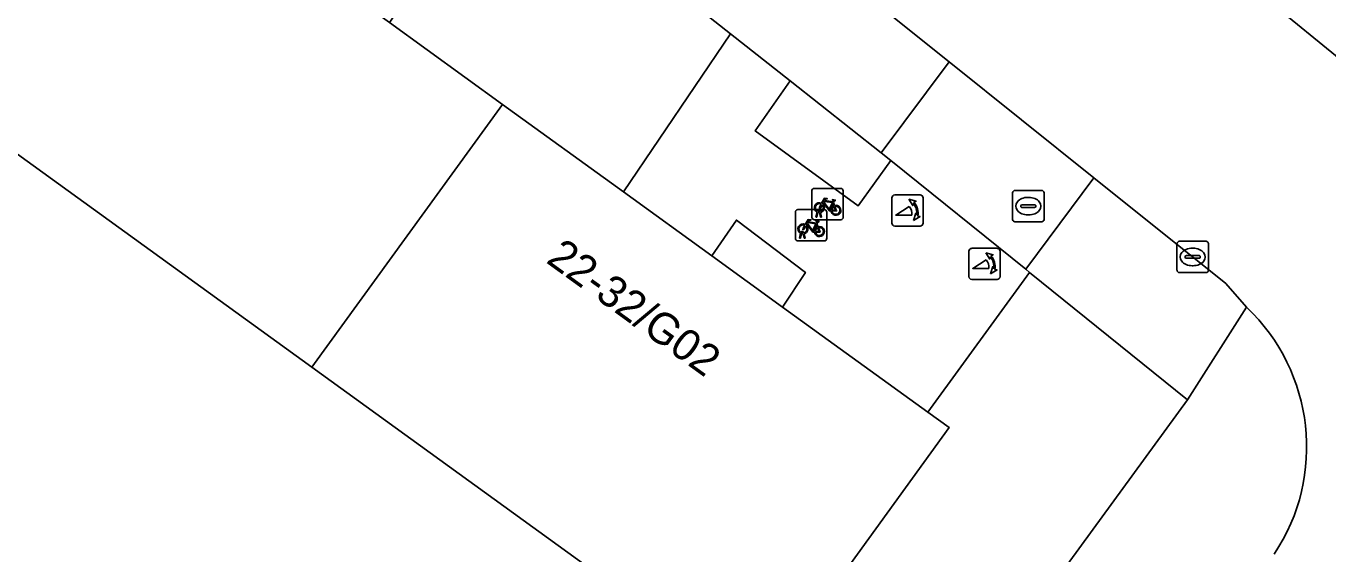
# Model space of a CAD drawing. Extents: x 159674 to 160531, y 382172 to 382904.
# Drawn here: x 160362.08 to 160403.62, y 382615.6 to 382632.46 of the extents above; entities that cross this region are included whole.
import ezdxf

# ---------------------------------------------------------------- set-up
doc = ezdxf.new("R2010")
doc.units = 0
for name, color, linetype in [('IMGEO_Brandkraan', 7, 'Continuous'), ('IMGEO_Fietsenrek', 7, 'Continuous'), ('IMGEO_Groenvoorziening', 7, 'Continuous'), ('IMGEO_Kolk', 7, 'Continuous'), ('IMGEO_Pand', 7, 'Continuous'), ('IMGEO_Pand_nummerreeks', 7, 'Continuous'), ('IMGEO_Poller', 7, 'Continuous'), ('IMGEO_Rijbaan_lokaal_gesloten', 7, 'Continuous'), ('IMGEO_Voetpad_open', 7, 'Continuous')]:
    doc.layers.add(name, color=color, linetype=linetype)

msp = doc.modelspace()

# ---------------------------------------------------------------- linework, layer by layer
at = {"layer": 'IMGEO_Brandkraan'}
for p, q in [((160393.557, 382626.284), (160393.557, 382627.136)), ((160393.632, 382627.21), (160394.484, 382627.21)), ((160394.558, 382627.136), (160394.558, 382626.284)), ((160393.816, 382626.704), (160393.816, 382626.716)), ((160394.254, 382626.667), (160393.856, 382626.667)), ((160393.859, 382626.753), (160394.257, 382626.753)), ((160394.045, 382626.99), (160394.07, 382626.99)), ((160394.3, 382626.716), (160394.3, 382626.704)), ((160394.484, 382626.21), (160393.632, 382626.21)), ((160394.068, 382626.43), (160394.043, 382626.43))]:
    msp.add_line(p, q, dxfattribs=at)
for points in [[(160393.557, 382626.284), (160393.557, 382627.136)], [(160393.632, 382627.21), (160394.484, 382627.21)], [(160394.558, 382627.136), (160394.558, 382626.284)], [(160394.484, 382626.21), (160393.632, 382626.21)]]:
    msp.add_lwpolyline(points, dxfattribs=at)
for centre, radius, start, end in [((160393.634, 382627.134), 0.0765, 91.552, 178.448), ((160393.634, 382627.134), 0.0765, 91.552, 178.448), ((160394.482, 382627.134), 0.0765, 1.552, 88.448), ((160394.482, 382627.134), 0.0765, 1.552, 88.448), ((160393.856, 382626.713), 0.0403, 85.8775, 175.7526), ((160393.853, 382626.703), 0.0366, 178.938, 274.7102), ((160394.257, 382626.71), 0.043, 264.8664, 352.4533), ((160394.261, 382626.715), 0.0386, 1.7309, 96.639), ((160393.634, 382626.286), 0.0765, 181.552, 268.448), ((160393.634, 382626.286), 0.0765, 181.552, 268.448), ((160394.482, 382626.286), 0.0765, 271.552, 358.448), ((160394.482, 382626.286), 0.0765, 271.552, 358.448)]:
    msp.add_arc(centre, radius, start, end, dxfattribs=at)
for centre, major_axis, ratio, start_param, end_param in [((160394.044, 382626.71), (-0.387, 0.002), 0.722429, 4.712389, 7.853982), ((160394.069, 382626.71), (-0.39, 0.002), 0.717154, 1.570796, 4.712389)]:
    msp.add_ellipse(centre, major_axis=major_axis, ratio=ratio, start_param=start_param, end_param=end_param, dxfattribs=at)
at = {"layer": 'IMGEO_Fietsenrek'}
for p, q in [((160387.15, 382626.351), (160387.15, 382627.192)), ((160387.15, 382627.192), (160387.15, 382626.351)), ((160387.225, 382627.276), (160388.066, 382627.276)), ((160388.066, 382627.276), (160387.225, 382627.276)), ((160388.15, 382627.201), (160388.15, 382626.36)), ((160388.15, 382626.36), (160388.15, 382627.201)), ((160387.837, 382626.825), (160387.873, 382626.73)), ((160386.625, 382625.673), (160386.625, 382626.514)), ((160386.625, 382626.514), (160386.625, 382625.673)), ((160386.7, 382626.598), (160387.541, 382626.598)), ((160387.541, 382626.598), (160386.7, 382626.598)), ((160388.075, 382626.276), (160387.234, 382626.276)), ((160387.234, 382626.276), (160388.075, 382626.276)), ((160387.277, 382626.36), (160387.316, 382626.52)), ((160387.311, 382626.36), (160387.277, 382626.36)), ((160387.346, 382626.508), (160387.311, 382626.36)), ((160387.388, 382626.532), (160387.387, 382626.536)), ((160387.429, 382626.36), (160387.395, 382626.502)), ((160387.419, 382626.543), (160387.42, 382626.536)), ((160387.427, 382626.506), (160387.462, 382626.36)), ((160387.462, 382626.36), (160387.429, 382626.36)), ((160387.625, 382626.523), (160387.625, 382625.682)), ((160387.625, 382625.682), (160387.625, 382626.523)), ((160386.752, 382625.682), (160386.791, 382625.842)), ((160386.821, 382625.83), (160386.786, 382625.682)), ((160386.863, 382625.854), (160386.862, 382625.858)), ((160386.904, 382625.682), (160386.87, 382625.824)), ((160386.894, 382625.865), (160386.895, 382625.858)), ((160386.902, 382625.828), (160386.937, 382625.682)), ((160387.312, 382626.147), (160387.348, 382626.052)), ((160387.55, 382625.598), (160386.709, 382625.598)), ((160386.709, 382625.598), (160387.55, 382625.598)), ((160386.786, 382625.682), (160386.752, 382625.682)), ((160386.937, 382625.682), (160386.904, 382625.682))]:
    msp.add_line(p, q, dxfattribs=at)
for points in [[(160387.484, 382626.75), (160387.432, 382626.66), (160387.392, 382626.635), (160387.393, 382626.682), (160387.448, 382626.776)], [(160387.463, 382626.802), (160387.558, 382626.966), (160387.644, 382626.952), (160387.646, 382626.943), (160387.59, 382626.932), (160387.563, 382626.887), (160387.819, 382626.846)], [(160387.759, 382626.558), (160387.709, 382626.558), (160387.518, 382626.809), (160387.499, 382626.777)], [(160387.806, 382626.821), (160387.549, 382626.862), (160387.532, 382626.833), (160387.699, 382626.613), (160387.806, 382626.821)], [(160387.854, 382626.723), (160387.824, 382626.8), (160387.715, 382626.582), (160387.758, 382626.582)], [(160387.788, 382626.582), (160387.908, 382626.581), (160387.864, 382626.695)], [(160387.884, 382626.702), (160387.939, 382626.557), (160387.789, 382626.557)], [(160387.819, 382626.846), (160387.844, 382626.895), (160387.838, 382626.899), (160387.815, 382626.903), (160387.803, 382626.91), (160387.802, 382626.913), (160387.804, 382626.918), (160387.899, 382626.903), (160387.901, 382626.893), (160387.891, 382626.88), (160387.879, 382626.874), (160387.865, 382626.88), (160387.837, 382626.825)], [(160386.938, 382626.124), (160387.033, 382626.288), (160387.119, 382626.274), (160387.121, 382626.265), (160387.065, 382626.254), (160387.038, 382626.209), (160387.294, 382626.168)], [(160387.294, 382626.168), (160387.319, 382626.217), (160387.313, 382626.221), (160387.29, 382626.225), (160387.278, 382626.232), (160387.277, 382626.235), (160387.279, 382626.24), (160387.374, 382626.225), (160387.376, 382626.215), (160387.366, 382626.202), (160387.354, 382626.196), (160387.34, 382626.202), (160387.312, 382626.147)], [(160386.959, 382626.072), (160386.907, 382625.982), (160386.867, 382625.957), (160386.868, 382626.004), (160386.923, 382626.098)], [(160387.234, 382625.88), (160387.184, 382625.88), (160386.993, 382626.131), (160386.974, 382626.099)], [(160387.281, 382626.143), (160387.024, 382626.184), (160387.007, 382626.155), (160387.174, 382625.935), (160387.281, 382626.143)], [(160387.329, 382626.045), (160387.299, 382626.122), (160387.19, 382625.904), (160387.233, 382625.904)], [(160387.263, 382625.904), (160387.383, 382625.903), (160387.339, 382626.017)], [(160387.359, 382626.024), (160387.414, 382625.879), (160387.264, 382625.879)]]:
    msp.add_lwpolyline(points, dxfattribs=at)
for centre, radius, start, end in [((160387.228, 382627.198), 0.0779, 92.4484, 184.2845), ((160387.228, 382627.198), 0.0779, 92.4484, 184.2845), ((160388.072, 382627.198), 0.0779, 2.4484, 94.2845), ((160388.072, 382627.198), 0.0779, 2.4484, 94.2845), ((160387.39, 382626.661), 0.159, 62.6766, 242.1369), ((160387.39, 382626.661), 0.129, 63.3192, 238.903), ((160387.39, 382626.661), 0.129, 283.6043, 43.4302), ((160387.39, 382626.661), 0.159, 283.5766, 46.6042), ((160387.917, 382626.577), 0.159, 113.3408, 178.3217), ((160387.917, 382626.577), 0.159, 187.0065, 105.7708), ((160387.917, 382626.577), 0.129, 113.923, 177.9556), ((160387.917, 382626.577), 0.129, 188.6715, 104.5883), ((160386.703, 382626.52), 0.0779, 92.4484, 184.2845), ((160386.703, 382626.52), 0.0779, 92.4484, 184.2845), ((160387.228, 382626.354), 0.0779, 182.4484, 274.2845), ((160387.228, 382626.354), 0.0779, 182.4484, 274.2845), ((160387.37, 382626.532), 0.0499, 12.8025, 158.6934), ((160387.39, 382626.661), 0.159, 253.9967, 271.7867), ((160387.37, 382626.532), 0.0174, 12.8025, 163.4502), ((160387.39, 382626.661), 0.129, 253.415, 269.0204), ((160387.547, 382626.52), 0.0779, 2.4484, 94.2845), ((160387.547, 382626.52), 0.0779, 2.4484, 94.2845), ((160388.072, 382626.354), 0.0779, 272.4484, 4.2845), ((160388.072, 382626.354), 0.0779, 272.4484, 4.2845), ((160386.865, 382625.983), 0.159, 62.6766, 242.1369), ((160386.865, 382625.983), 0.129, 63.3192, 238.903), ((160386.845, 382625.854), 0.0499, 12.8025, 158.6934), ((160386.865, 382625.983), 0.159, 253.9967, 271.7867), ((160386.845, 382625.854), 0.0174, 12.8025, 163.4502), ((160386.865, 382625.983), 0.129, 253.415, 269.0204), ((160386.865, 382625.983), 0.129, 283.6043, 43.4302), ((160386.865, 382625.983), 0.159, 283.5766, 46.6042), ((160387.392, 382625.899), 0.159, 113.3408, 178.3217), ((160387.392, 382625.899), 0.159, 187.0065, 105.7708), ((160387.392, 382625.899), 0.129, 113.923, 177.9556), ((160387.392, 382625.899), 0.129, 188.6715, 104.5883), ((160386.703, 382625.676), 0.0779, 182.4484, 274.2845), ((160386.703, 382625.676), 0.0779, 182.4484, 274.2845), ((160387.547, 382625.676), 0.0779, 272.4484, 4.2845), ((160387.547, 382625.676), 0.0779, 272.4484, 4.2845)]:
    msp.add_arc(centre, radius, start, end, dxfattribs=at)
at = {"layer": 'IMGEO_Groenvoorziening'}
for points in [[(160399.135, 382620.521), (160394.097, 382624.593), (160390.852, 382620.13), (160391.536, 382619.635), (160385.454, 382611.238), (160381.405, 382614.171), (160371.199, 382621.562), (160356.943, 382631.886), (160360.093, 382636.235), (160363.025, 382640.284), (160363.685, 382639.806), (160368.154, 382645.167), (160368.401, 382645.464), (160368.041, 382645.751), (160367.072, 382646.525), (160363.098, 382641.755), (160342.684, 382657.705), (160337.191, 382650.136), (160341.198, 382647.23), (160341.661, 382647.868), (160350.057, 382641.78), (160339.718, 382627.522), (160329.387, 382613.273)], [(160343.467, 382554.933), (160344.044, 382554.45), (160341.99, 382551.571), (160346.474, 382548.259), (160399.135, 382620.521)]]:
    msp.add_lwpolyline(points, dxfattribs=at)
for points in [[(160384.552, 382632.213), (160377.395, 382637.867), (160373.677, 382632.57), (160377.281, 382629.959), (160381.138, 382627.166)], [(160386.458, 382630.707), (160385.343, 382629.114), (160388.624, 382626.718), (160389.672, 382628.168), (160389.367, 382628.409)], [(160386.216, 382623.488), (160386.946, 382624.592), (160384.743, 382626.263), (160383.956, 382625.125)]]:
    msp.add_lwpolyline(points, close=True, dxfattribs=at)
at = {"layer": 'IMGEO_Kolk'}
for p, q in [((160398.801, 382624.66), (160398.801, 382625.512)), ((160398.876, 382625.586), (160399.728, 382625.586)), ((160399.802, 382625.512), (160399.802, 382624.66)), ((160399.06, 382625.08), (160399.06, 382625.092)), ((160399.498, 382625.043), (160399.1, 382625.043)), ((160399.103, 382625.129), (160399.501, 382625.129)), ((160399.289, 382625.366), (160399.314, 382625.366)), ((160399.544, 382625.092), (160399.544, 382625.08)), ((160399.728, 382624.586), (160398.876, 382624.586)), ((160399.312, 382624.806), (160399.287, 382624.806))]:
    msp.add_line(p, q, dxfattribs=at)
for points in [[(160398.801, 382624.66), (160398.801, 382625.512)], [(160398.876, 382625.586), (160399.728, 382625.586)], [(160399.802, 382625.512), (160399.802, 382624.66)], [(160399.728, 382624.586), (160398.876, 382624.586)]]:
    msp.add_lwpolyline(points, dxfattribs=at)
for centre, radius, start, end in [((160398.878, 382625.51), 0.0765, 91.552, 178.448), ((160398.878, 382625.51), 0.0765, 91.552, 178.448), ((160399.726, 382625.51), 0.0765, 1.552, 88.448), ((160399.726, 382625.51), 0.0765, 1.552, 88.448), ((160399.1, 382625.089), 0.0403, 85.8775, 175.7526), ((160399.097, 382625.079), 0.0366, 178.938, 274.7102), ((160399.501, 382625.086), 0.043, 264.8664, 352.4533), ((160399.505, 382625.091), 0.0386, 1.7309, 96.639), ((160398.878, 382624.662), 0.0765, 181.552, 268.448), ((160398.878, 382624.662), 0.0765, 181.552, 268.448), ((160399.726, 382624.662), 0.0765, 271.552, 358.448), ((160399.726, 382624.662), 0.0765, 271.552, 358.448)]:
    msp.add_arc(centre, radius, start, end, dxfattribs=at)
for centre, major_axis, ratio, start_param, end_param in [((160399.288, 382625.086), (-0.387, 0.002), 0.722429, 4.712389, 7.853982), ((160399.313, 382625.086), (-0.39, 0.002), 0.717154, 1.570796, 4.712389)]:
    msp.add_ellipse(centre, major_axis=major_axis, ratio=ratio, start_param=start_param, end_param=end_param, dxfattribs=at)
at = {"layer": 'IMGEO_Pand'}
for points in [[(160371.199, 382621.562), (160377.281, 382629.959), (160373.677, 382632.57), (160370.844, 382634.621), (160368.647, 382636.212), (160363.685, 382639.806), (160363.025, 382640.284), (160360.093, 382636.235), (160356.943, 382631.886)], [(160371.199, 382621.562), (160381.405, 382614.171), (160385.454, 382611.238), (160391.536, 382619.635), (160390.852, 382620.13), (160386.216, 382623.488), (160383.956, 382625.125), (160381.138, 382627.166), (160377.281, 382629.959)]]:
    msp.add_lwpolyline(points, close=True, dxfattribs=at)
at = {"layer": 'IMGEO_Poller'}
for p, q in [((160390.605, 382627.07), (160389.797, 382627.07)), ((160390.605, 382627.07), (160389.797, 382627.07)), ((160389.703, 382626.975), (160389.703, 382626.168)), ((160389.703, 382626.975), (160389.703, 382626.168)), ((160390.699, 382626.168), (160390.699, 382626.975)), ((160390.699, 382626.168), (160390.699, 382626.975)), ((160389.797, 382626.073), (160390.605, 382626.073)), ((160389.797, 382626.073), (160390.605, 382626.073)), ((160392.16, 382625.267), (160392.16, 382624.46)), ((160392.16, 382625.267), (160392.16, 382624.46)), ((160393.062, 382625.362), (160392.254, 382625.362)), ((160393.062, 382625.362), (160392.254, 382625.362)), ((160393.156, 382624.46), (160393.156, 382625.267)), ((160393.156, 382624.46), (160393.156, 382625.267)), ((160392.254, 382624.365), (160393.062, 382624.365)), ((160392.254, 382624.365), (160393.062, 382624.365))]:
    msp.add_line(p, q, dxfattribs=at)
for points in [[(160390.338, 382626.426), (160389.825, 382626.426), (160390.255, 382626.701)], [(160390.382, 382626.799), (160390.37, 382626.726), (160390.245, 382626.931)], [(160390.245, 382626.931), (160390.476, 382626.865), (160390.405, 382626.833)], [(160390.398, 382626.254), (160390.464, 382626.485), (160390.494, 382626.417)], [(160390.53, 382626.39), (160390.602, 382626.379), (160390.398, 382626.254)], [(160392.795, 382624.718), (160392.282, 382624.718), (160392.712, 382624.993)], [(160392.839, 382625.091), (160392.827, 382625.018), (160392.702, 382625.223)], [(160392.702, 382625.223), (160392.933, 382625.157), (160392.862, 382625.125)], [(160392.855, 382624.546), (160392.921, 382624.777), (160392.951, 382624.709)], [(160392.987, 382624.682), (160393.059, 382624.671), (160392.855, 382624.546)]]:
    msp.add_lwpolyline(points, dxfattribs=at)
for centre, radius, start, end in [((160389.797, 382626.975), 0.0946, 90, 180), ((160389.797, 382626.975), 0.0946, 90, 180), ((160390.605, 382626.975), 0.0946, 0, 90), ((160390.605, 382626.975), 0.0946, 0, 90), ((160390.01, 382626.476), 0.332, 351.3247, 42.4854), ((160390.024, 382626.486), 0.476, 351.7527, 41.1691), ((160390.024, 382626.486), 0.516, 349.3569, 42.2912), ((160389.797, 382626.168), 0.0946, 180, 270), ((160389.797, 382626.168), 0.0946, 180, 270), ((160390.605, 382626.168), 0.0946, 270, 0), ((160390.605, 382626.168), 0.0946, 270, 0), ((160392.254, 382625.267), 0.0946, 90, 180), ((160392.254, 382625.267), 0.0946, 90, 180), ((160392.467, 382624.768), 0.332, 351.3247, 42.4854), ((160392.481, 382624.778), 0.476, 351.7527, 41.1691), ((160392.481, 382624.778), 0.516, 349.3569, 42.2912), ((160393.062, 382625.267), 0.0946, 0, 90), ((160393.062, 382625.267), 0.0946, 0, 90), ((160392.254, 382624.46), 0.0946, 180, 270), ((160392.254, 382624.46), 0.0946, 180, 270), ((160393.062, 382624.46), 0.0946, 270, 0), ((160393.062, 382624.46), 0.0946, 270, 0)]:
    msp.add_arc(centre, radius, start, end, dxfattribs=at)
at = {"layer": 'IMGEO_Rijbaan_lokaal_gesloten'}
for points in [[(160384.589, 382647.265), (160379.847, 382640.684), (160391.528, 382631.318), (160396.148, 382627.615), (160400.355, 382624.242), (160401.023, 382623.483)], [(160406.571, 382629.307), (160384.589, 382647.265)]]:
    msp.add_lwpolyline(points, dxfattribs=at)
msp.add_arc((160396.769, 382619.016), 6.169, 326.3585, 46.3936, dxfattribs=at)
at = {"layer": 'IMGEO_Voetpad_open'}
for points in [[(160378.286, 382657.664), (160376.754, 382655.854), (160377.969, 382654.877), (160376.836, 382653.466), (160382.462, 382648.966), (160384.589, 382647.265), (160406.571, 382629.307), (160410.553, 382632.042), (160406.072, 382635.422)], [(160379.847, 382640.684), (160377.722, 382642.387), (160375.287, 382644.339), (160372.955, 382641.374), (160375.524, 382639.345), (160377.395, 382637.867), (160384.552, 382632.213), (160386.458, 382630.707), (160389.367, 382628.409), (160391.528, 382631.318)], [(160389.672, 382628.168), (160388.624, 382626.718), (160385.343, 382629.114), (160386.458, 382630.707), (160384.552, 382632.213), (160381.138, 382627.166), (160383.956, 382625.125), (160384.743, 382626.263), (160386.946, 382624.592), (160386.216, 382623.488), (160390.852, 382620.13), (160394.097, 382624.593), (160393.973, 382624.693)], [(160391.528, 382631.318), (160389.367, 382628.409), (160389.672, 382628.168), (160393.973, 382624.693), (160396.148, 382627.615)], [(160400.355, 382624.242), (160396.148, 382627.615), (160393.973, 382624.693), (160394.097, 382624.593), (160399.135, 382620.521), (160401.023, 382623.483)]]:
    msp.add_lwpolyline(points, close=True, dxfattribs=at)
msp.add_lwpolyline([(160401.023, 382623.483), (160399.135, 382620.521), (160346.474, 382548.259), (160344.923, 382546.056), (160311.42, 382500), (160295.603, 382478.257), (160293.955, 382476.039), (160288.608, 382468.68), (160248.967, 382414.122), (160246.396, 382412.259)], dxfattribs=at)
msp.add_arc((160396.769, 382619.016), 6.169, 326.3585, 46.3936, dxfattribs=at)

# ---------------------------------------------------------------- texts
at = {"layer": 'IMGEO_Pand_nummerreeks'}
msp.add_text('22-32/G02', height=1, rotation=324.0862, dxfattribs=at).set_placement((160378.636, 382624.928))

doc.saveas('drawing.dxf')
